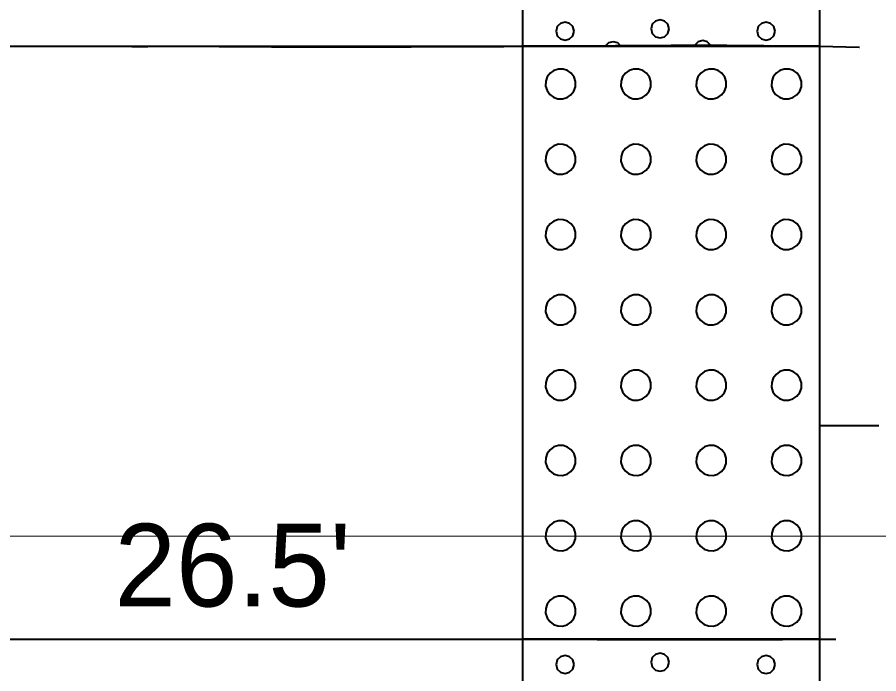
# Model space of a CAD drawing. Extents: x -582 to 653, y -817 to -3.
# Drawn here: x -72.08 to -64.82, y -720.71 to -715.18 of the extents above; entities that cross this region are included whole.
import ezdxf

# ---------------------------------------------------------------- set-up
doc = ezdxf.new("R2010")
doc.units = 0
doc.header["$LTSCALE"] = 0.4
doc.linetypes.add('LONG_DASHED', pattern=[7.5, 6, -1.5])
for name, color, linetype, lineweight in [('26', 7, 'LONG_DASHED', 40), ('27', 7, 'Continuous', 40), ('7', 7, 'Continuous', 13)]:
    doc.layers.add(name, color=color, linetype=linetype, lineweight=lineweight)

msp = doc.modelspace()

# ---------------------------------------------------------------- linework, layer by layer
at = {"layer": '26'}
for points in [[(-88.3808, -715.5103), (-71.5863, -715.4226), (-67.8189, -715.4226), (-65.3189, -715.4226), (-59.9854, -716.0123), (-56.4736, -717.0164)], [(-88.5815, -720.4304), (-71.5863, -720.4226), (-67.8189, -720.4226), (-65.3189, -720.4226), (-45.0863, -720.1526), (-41.3189, -720.1526), (-38.8189, -720.1526), (-13.429, -720.33)]]:
    msp.add_spline(points, degree=3, dxfattribs=at)
at = {"layer": '27'}
for p, q in [((-71.5863, -715.4226), (-67.8189, -715.4226)), ((-64.8189, -718.6226), (-65.3189, -718.6226)), ((-71.5863, -720.4226), (-67.8189, -720.4226))]:
    msp.add_line(p, q, dxfattribs=at)
for points in [[(-67.8189, -704.9226), (-65.3189, -704.9226), (-65.3189, -715.4226), (-67.8189, -715.4226)], [(-67.387, -715.2953), (-67.3972, -715.2572), (-67.4251, -715.2293), (-67.4632, -715.2191), (-67.5013, -715.2293), (-67.5292, -715.2572), (-67.5394, -715.2953), (-67.5292, -715.3334), (-67.5013, -715.3612), (-67.4632, -715.3715), (-67.4251, -715.3612), (-67.3972, -715.3334)], [(-66.586, -715.2757), (-66.5962, -715.2376), (-66.6241, -715.2097), (-66.6622, -715.1995), (-66.7003, -715.2097), (-66.7282, -715.2376), (-66.7384, -715.2757), (-66.7282, -715.3138), (-66.7003, -715.3417), (-66.6622, -715.3519), (-66.6241, -715.3417), (-66.5962, -715.3138)], [(-65.6924, -715.2953), (-65.7026, -715.2572), (-65.7305, -715.2293), (-65.7686, -715.2191), (-65.8067, -715.2293), (-65.8345, -715.2572), (-65.8448, -715.2953), (-65.8345, -715.3334), (-65.8067, -715.3613), (-65.7686, -715.3715), (-65.7305, -715.3613), (-65.7026, -715.3334)], [(-66.2372, -715.4134), (-66.265, -715.3855), (-66.3031, -715.3753), (-66.3412, -715.3855), (-66.3691, -715.4134), (-66.3716, -715.4226), (-66.2347, -715.4226)], [(-67.8189, -715.4226), (-65.3189, -715.4226), (-65.3189, -720.4226), (-67.8189, -720.4226)], [(-66.9922, -715.4224), (-67.0201, -715.3945), (-67.0582, -715.3843), (-67.0963, -715.3945), (-67.1242, -715.4224), (-67.1243, -715.4226), (-66.9922, -715.4226)], [(-67.3743, -715.7401), (-67.3758, -715.7204), (-67.388, -715.6827), (-67.4111, -715.6506), (-67.443, -715.6272), (-67.4805, -715.6147), (-67.5201, -715.6144), (-67.5578, -715.6262), (-67.5901, -715.6491), (-67.6138, -715.6808), (-67.6266, -715.7182), (-67.6273, -715.7577), (-67.6158, -715.7956), (-67.5932, -715.8281), (-67.5618, -715.852), (-67.5245, -715.8652), (-67.4849, -715.8662), (-67.447, -715.855), (-67.4143, -715.8327), (-67.39, -715.8015), (-67.3766, -715.7643)], [(-66.7393, -715.7401), (-66.7408, -715.7204), (-66.753, -715.6827), (-66.7761, -715.6506), (-66.808, -715.6272), (-66.8455, -715.6147), (-66.8851, -715.6144), (-66.9228, -715.6262), (-66.9551, -715.6491), (-66.9788, -715.6808), (-66.9916, -715.7182), (-66.9923, -715.7577), (-66.9808, -715.7956), (-66.9582, -715.8281), (-66.9268, -715.852), (-66.8895, -715.8652), (-66.8499, -715.8662), (-66.812, -715.855), (-66.7793, -715.8327), (-66.755, -715.8015), (-66.7416, -715.7643)], [(-66.1043, -715.7401), (-66.1058, -715.7204), (-66.118, -715.6827), (-66.1411, -715.6506), (-66.173, -715.6272), (-66.2105, -715.6147), (-66.2501, -715.6144), (-66.2878, -715.6262), (-66.3201, -715.6491), (-66.3438, -715.6808), (-66.3566, -715.7182), (-66.3573, -715.7577), (-66.3458, -715.7956), (-66.3232, -715.8281), (-66.2918, -715.852), (-66.2545, -715.8652), (-66.2149, -715.8662), (-66.177, -715.855), (-66.1443, -715.8327), (-66.12, -715.8015), (-66.1066, -715.7643)], [(-65.4693, -715.7401), (-65.4708, -715.7204), (-65.483, -715.6827), (-65.5061, -715.6506), (-65.538, -715.6272), (-65.5755, -715.6147), (-65.6151, -715.6144), (-65.6528, -715.6262), (-65.6851, -715.6491), (-65.7088, -715.6808), (-65.7216, -715.7182), (-65.7223, -715.7577), (-65.7108, -715.7956), (-65.6882, -715.8281), (-65.6568, -715.852), (-65.6195, -715.8652), (-65.5799, -715.8662), (-65.542, -715.855), (-65.5093, -715.8327), (-65.485, -715.8015), (-65.4716, -715.7643)], [(-67.3743, -716.3751), (-67.3758, -716.3554), (-67.388, -716.3177), (-67.4111, -716.2856), (-67.443, -716.2622), (-67.4805, -716.2497), (-67.5201, -716.2494), (-67.5578, -716.2612), (-67.5901, -716.2841), (-67.6138, -716.3158), (-67.6266, -716.3532), (-67.6273, -716.3927), (-67.6158, -716.4306), (-67.5932, -716.4631), (-67.5618, -716.487), (-67.5245, -716.5002), (-67.4849, -716.5012), (-67.447, -716.49), (-67.4143, -716.4677), (-67.39, -716.4365), (-67.3766, -716.3993)], [(-66.7393, -716.3751), (-66.7408, -716.3554), (-66.753, -716.3177), (-66.7761, -716.2856), (-66.808, -716.2622), (-66.8455, -716.2497), (-66.8851, -716.2494), (-66.9228, -716.2612), (-66.9551, -716.2841), (-66.9788, -716.3158), (-66.9916, -716.3532), (-66.9923, -716.3927), (-66.9808, -716.4306), (-66.9582, -716.4631), (-66.9268, -716.487), (-66.8895, -716.5002), (-66.8499, -716.5012), (-66.812, -716.49), (-66.7793, -716.4677), (-66.755, -716.4365), (-66.7416, -716.3993)], [(-66.1043, -716.3751), (-66.1058, -716.3554), (-66.118, -716.3177), (-66.1411, -716.2856), (-66.173, -716.2622), (-66.2105, -716.2497), (-66.2501, -716.2494), (-66.2878, -716.2612), (-66.3201, -716.2841), (-66.3438, -716.3158), (-66.3566, -716.3532), (-66.3573, -716.3927), (-66.3458, -716.4306), (-66.3232, -716.4631), (-66.2918, -716.487), (-66.2545, -716.5002), (-66.2149, -716.5012), (-66.177, -716.49), (-66.1443, -716.4677), (-66.12, -716.4365), (-66.1066, -716.3993)], [(-65.4693, -716.3751), (-65.4708, -716.3554), (-65.483, -716.3177), (-65.5061, -716.2856), (-65.538, -716.2622), (-65.5755, -716.2497), (-65.6151, -716.2494), (-65.6528, -716.2612), (-65.6851, -716.2841), (-65.7088, -716.3158), (-65.7216, -716.3532), (-65.7223, -716.3927), (-65.7108, -716.4306), (-65.6882, -716.4631), (-65.6568, -716.487), (-65.6195, -716.5002), (-65.5799, -716.5012), (-65.542, -716.49), (-65.5093, -716.4677), (-65.485, -716.4365), (-65.4716, -716.3993)], [(-67.3743, -717.0101), (-67.3758, -716.9904), (-67.388, -716.9527), (-67.4111, -716.9206), (-67.443, -716.8972), (-67.4805, -716.8847), (-67.5201, -716.8844), (-67.5578, -716.8962), (-67.5901, -716.9191), (-67.6138, -716.9508), (-67.6266, -716.9882), (-67.6273, -717.0277), (-67.6158, -717.0656), (-67.5932, -717.0981), (-67.5618, -717.122), (-67.5245, -717.1352), (-67.4849, -717.1362), (-67.447, -717.125), (-67.4143, -717.1027), (-67.39, -717.0715), (-67.3766, -717.0343)], [(-66.7393, -717.0101), (-66.7408, -716.9904), (-66.753, -716.9527), (-66.7761, -716.9206), (-66.808, -716.8972), (-66.8455, -716.8847), (-66.8851, -716.8844), (-66.9228, -716.8962), (-66.9551, -716.9191), (-66.9788, -716.9508), (-66.9916, -716.9882), (-66.9923, -717.0277), (-66.9808, -717.0656), (-66.9582, -717.0981), (-66.9268, -717.122), (-66.8895, -717.1352), (-66.8499, -717.1362), (-66.812, -717.125), (-66.7793, -717.1027), (-66.755, -717.0715), (-66.7416, -717.0343)], [(-66.1043, -717.0101), (-66.1058, -716.9904), (-66.118, -716.9527), (-66.1411, -716.9206), (-66.173, -716.8972), (-66.2105, -716.8847), (-66.2501, -716.8844), (-66.2878, -716.8962), (-66.3201, -716.9191), (-66.3438, -716.9508), (-66.3566, -716.9882), (-66.3573, -717.0277), (-66.3458, -717.0656), (-66.3232, -717.0981), (-66.2918, -717.122), (-66.2545, -717.1352), (-66.2149, -717.1362), (-66.177, -717.125), (-66.1443, -717.1027), (-66.12, -717.0715), (-66.1066, -717.0343)], [(-65.4693, -717.0101), (-65.4708, -716.9904), (-65.483, -716.9527), (-65.5061, -716.9206), (-65.538, -716.8972), (-65.5755, -716.8847), (-65.6151, -716.8844), (-65.6528, -716.8962), (-65.6851, -716.9191), (-65.7088, -716.9508), (-65.7216, -716.9882), (-65.7223, -717.0277), (-65.7108, -717.0656), (-65.6882, -717.0981), (-65.6568, -717.122), (-65.6195, -717.1352), (-65.5799, -717.1362), (-65.542, -717.125), (-65.5093, -717.1027), (-65.485, -717.0715), (-65.4716, -717.0343)], [(-67.3743, -717.6451), (-67.3758, -717.6254), (-67.388, -717.5877), (-67.4111, -717.5556), (-67.443, -717.5322), (-67.4805, -717.5197), (-67.5201, -717.5194), (-67.5578, -717.5312), (-67.5901, -717.5541), (-67.6138, -717.5858), (-67.6266, -717.6232), (-67.6273, -717.6627), (-67.6158, -717.7006), (-67.5932, -717.7331), (-67.5618, -717.757), (-67.5245, -717.7702), (-67.4849, -717.7712), (-67.447, -717.76), (-67.4143, -717.7377), (-67.39, -717.7065), (-67.3766, -717.6693)], [(-66.7393, -717.6451), (-66.7408, -717.6254), (-66.753, -717.5877), (-66.7761, -717.5556), (-66.808, -717.5322), (-66.8455, -717.5197), (-66.8851, -717.5194), (-66.9228, -717.5312), (-66.9551, -717.5541), (-66.9788, -717.5858), (-66.9916, -717.6232), (-66.9923, -717.6627), (-66.9808, -717.7006), (-66.9582, -717.7331), (-66.9268, -717.757), (-66.8895, -717.7702), (-66.8499, -717.7712), (-66.812, -717.76), (-66.7793, -717.7377), (-66.755, -717.7065), (-66.7416, -717.6693)], [(-66.1043, -717.6451), (-66.1058, -717.6254), (-66.118, -717.5877), (-66.1411, -717.5556), (-66.173, -717.5322), (-66.2105, -717.5197), (-66.2501, -717.5194), (-66.2878, -717.5312), (-66.3201, -717.5541), (-66.3438, -717.5858), (-66.3566, -717.6232), (-66.3573, -717.6627), (-66.3458, -717.7006), (-66.3232, -717.7331), (-66.2918, -717.757), (-66.2545, -717.7702), (-66.2149, -717.7712), (-66.177, -717.76), (-66.1443, -717.7377), (-66.12, -717.7065), (-66.1066, -717.6693)], [(-65.4693, -717.6451), (-65.4708, -717.6254), (-65.483, -717.5877), (-65.5061, -717.5556), (-65.538, -717.5322), (-65.5755, -717.5197), (-65.6151, -717.5194), (-65.6528, -717.5312), (-65.6851, -717.5541), (-65.7088, -717.5858), (-65.7216, -717.6232), (-65.7223, -717.6627), (-65.7108, -717.7006), (-65.6882, -717.7331), (-65.6568, -717.757), (-65.6195, -717.7702), (-65.5799, -717.7712), (-65.542, -717.76), (-65.5093, -717.7377), (-65.485, -717.7065), (-65.4716, -717.6693)], [(-67.3743, -718.2801), (-67.3758, -718.2604), (-67.388, -718.2227), (-67.4111, -718.1906), (-67.443, -718.1672), (-67.4805, -718.1547), (-67.5201, -718.1544), (-67.5578, -718.1662), (-67.5901, -718.1891), (-67.6138, -718.2208), (-67.6266, -718.2582), (-67.6273, -718.2977), (-67.6158, -718.3356), (-67.5932, -718.3681), (-67.5618, -718.392), (-67.5245, -718.4052), (-67.4849, -718.4062), (-67.447, -718.395), (-67.4143, -718.3727), (-67.39, -718.3415), (-67.3766, -718.3043)], [(-66.7393, -718.2801), (-66.7408, -718.2604), (-66.753, -718.2227), (-66.7761, -718.1906), (-66.808, -718.1672), (-66.8455, -718.1547), (-66.8851, -718.1544), (-66.9228, -718.1662), (-66.9551, -718.1891), (-66.9788, -718.2208), (-66.9916, -718.2582), (-66.9923, -718.2977), (-66.9808, -718.3356), (-66.9582, -718.3681), (-66.9268, -718.392), (-66.8895, -718.4052), (-66.8499, -718.4062), (-66.812, -718.395), (-66.7793, -718.3727), (-66.755, -718.3415), (-66.7416, -718.3043)], [(-66.1043, -718.2801), (-66.1058, -718.2604), (-66.118, -718.2227), (-66.1411, -718.1906), (-66.173, -718.1672), (-66.2105, -718.1547), (-66.2501, -718.1544), (-66.2878, -718.1662), (-66.3201, -718.1891), (-66.3438, -718.2208), (-66.3566, -718.2582), (-66.3573, -718.2977), (-66.3458, -718.3356), (-66.3232, -718.3681), (-66.2918, -718.392), (-66.2545, -718.4052), (-66.2149, -718.4062), (-66.177, -718.395), (-66.1443, -718.3727), (-66.12, -718.3415), (-66.1066, -718.3043)], [(-65.4693, -718.2801), (-65.4708, -718.2604), (-65.483, -718.2227), (-65.5061, -718.1906), (-65.538, -718.1672), (-65.5755, -718.1547), (-65.6151, -718.1544), (-65.6528, -718.1662), (-65.6851, -718.1891), (-65.7088, -718.2208), (-65.7216, -718.2582), (-65.7223, -718.2977), (-65.7108, -718.3356), (-65.6882, -718.3681), (-65.6568, -718.392), (-65.6195, -718.4052), (-65.5799, -718.4062), (-65.542, -718.395), (-65.5093, -718.3727), (-65.485, -718.3415), (-65.4716, -718.3043)], [(-67.3743, -718.9151), (-67.3758, -718.8954), (-67.388, -718.8577), (-67.4111, -718.8256), (-67.443, -718.8022), (-67.4805, -718.7897), (-67.5201, -718.7894), (-67.5578, -718.8012), (-67.5901, -718.8241), (-67.6138, -718.8558), (-67.6266, -718.8932), (-67.6273, -718.9327), (-67.6158, -718.9706), (-67.5932, -719.0031), (-67.5618, -719.027), (-67.5245, -719.0402), (-67.4849, -719.0412), (-67.447, -719.03), (-67.4143, -719.0077), (-67.39, -718.9765), (-67.3766, -718.9393)], [(-66.7393, -718.9151), (-66.7408, -718.8954), (-66.753, -718.8577), (-66.7761, -718.8256), (-66.808, -718.8022), (-66.8455, -718.7897), (-66.8851, -718.7894), (-66.9228, -718.8012), (-66.9551, -718.8241), (-66.9788, -718.8558), (-66.9916, -718.8932), (-66.9923, -718.9327), (-66.9808, -718.9706), (-66.9582, -719.0031), (-66.9268, -719.027), (-66.8895, -719.0402), (-66.8499, -719.0412), (-66.812, -719.03), (-66.7793, -719.0077), (-66.755, -718.9765), (-66.7416, -718.9393)], [(-66.1043, -718.9151), (-66.1058, -718.8954), (-66.118, -718.8577), (-66.1411, -718.8256), (-66.173, -718.8022), (-66.2105, -718.7897), (-66.2501, -718.7894), (-66.2878, -718.8012), (-66.3201, -718.8241), (-66.3438, -718.8558), (-66.3566, -718.8932), (-66.3573, -718.9327), (-66.3458, -718.9706), (-66.3232, -719.0031), (-66.2918, -719.027), (-66.2545, -719.0402), (-66.2149, -719.0412), (-66.177, -719.03), (-66.1443, -719.0077), (-66.12, -718.9765), (-66.1066, -718.9393)], [(-65.4693, -718.9151), (-65.4708, -718.8954), (-65.483, -718.8577), (-65.5061, -718.8256), (-65.538, -718.8022), (-65.5755, -718.7897), (-65.6151, -718.7894), (-65.6528, -718.8012), (-65.6851, -718.8241), (-65.7088, -718.8558), (-65.7216, -718.8932), (-65.7223, -718.9327), (-65.7108, -718.9706), (-65.6882, -719.0031), (-65.6568, -719.027), (-65.6195, -719.0402), (-65.5799, -719.0412), (-65.542, -719.03), (-65.5093, -719.0077), (-65.485, -718.9765), (-65.4716, -718.9393)], [(-67.3743, -719.5501), (-67.3758, -719.5304), (-67.388, -719.4927), (-67.4111, -719.4606), (-67.443, -719.4372), (-67.4805, -719.4247), (-67.5201, -719.4244), (-67.5578, -719.4362), (-67.5901, -719.4591), (-67.6138, -719.4908), (-67.6266, -719.5282), (-67.6273, -719.5677), (-67.6158, -719.6056), (-67.5932, -719.6381), (-67.5618, -719.662), (-67.5245, -719.6752), (-67.4849, -719.6762), (-67.447, -719.665), (-67.4143, -719.6427), (-67.39, -719.6115), (-67.3766, -719.5743)], [(-66.7393, -719.5501), (-66.7408, -719.5304), (-66.753, -719.4927), (-66.7761, -719.4606), (-66.808, -719.4372), (-66.8455, -719.4247), (-66.8851, -719.4244), (-66.9228, -719.4362), (-66.9551, -719.4591), (-66.9788, -719.4908), (-66.9916, -719.5282), (-66.9923, -719.5677), (-66.9808, -719.6056), (-66.9582, -719.6381), (-66.9268, -719.662), (-66.8895, -719.6752), (-66.8499, -719.6762), (-66.812, -719.665), (-66.7793, -719.6427), (-66.755, -719.6115), (-66.7416, -719.5743)], [(-66.1043, -719.5501), (-66.1058, -719.5304), (-66.118, -719.4927), (-66.1411, -719.4606), (-66.173, -719.4372), (-66.2105, -719.4247), (-66.2501, -719.4244), (-66.2878, -719.4362), (-66.3201, -719.4591), (-66.3438, -719.4908), (-66.3566, -719.5282), (-66.3573, -719.5677), (-66.3458, -719.6056), (-66.3232, -719.6381), (-66.2918, -719.662), (-66.2545, -719.6752), (-66.2149, -719.6762), (-66.177, -719.665), (-66.1443, -719.6427), (-66.12, -719.6115), (-66.1066, -719.5743)], [(-65.4693, -719.5501), (-65.4708, -719.5304), (-65.483, -719.4927), (-65.5061, -719.4606), (-65.538, -719.4372), (-65.5755, -719.4247), (-65.6151, -719.4244), (-65.6528, -719.4362), (-65.6851, -719.4591), (-65.7088, -719.4908), (-65.7216, -719.5282), (-65.7223, -719.5677), (-65.7108, -719.6056), (-65.6882, -719.6381), (-65.6568, -719.662), (-65.6195, -719.6752), (-65.5799, -719.6762), (-65.542, -719.665), (-65.5093, -719.6427), (-65.485, -719.6115), (-65.4716, -719.5743)], [(-67.3743, -720.1851), (-67.3758, -720.1654), (-67.388, -720.1277), (-67.4111, -720.0956), (-67.443, -720.0722), (-67.4805, -720.0597), (-67.5201, -720.0594), (-67.5578, -720.0712), (-67.5901, -720.0941), (-67.6138, -720.1258), (-67.6266, -720.1632), (-67.6273, -720.2027), (-67.6158, -720.2406), (-67.5932, -720.2731), (-67.5618, -720.297), (-67.5245, -720.3102), (-67.4849, -720.3112), (-67.447, -720.3), (-67.4143, -720.2777), (-67.39, -720.2465), (-67.3766, -720.2093)], [(-66.7393, -720.1851), (-66.7408, -720.1654), (-66.753, -720.1277), (-66.7761, -720.0956), (-66.808, -720.0722), (-66.8455, -720.0597), (-66.8851, -720.0594), (-66.9228, -720.0712), (-66.9551, -720.0941), (-66.9788, -720.1258), (-66.9916, -720.1632), (-66.9923, -720.2027), (-66.9808, -720.2406), (-66.9582, -720.2731), (-66.9268, -720.297), (-66.8895, -720.3102), (-66.8499, -720.3112), (-66.812, -720.3), (-66.7793, -720.2777), (-66.755, -720.2465), (-66.7416, -720.2093)], [(-66.1043, -720.1851), (-66.1058, -720.1654), (-66.118, -720.1277), (-66.1411, -720.0956), (-66.173, -720.0722), (-66.2105, -720.0597), (-66.2501, -720.0594), (-66.2878, -720.0712), (-66.3201, -720.0941), (-66.3438, -720.1258), (-66.3566, -720.1632), (-66.3573, -720.2027), (-66.3458, -720.2406), (-66.3232, -720.2731), (-66.2918, -720.297), (-66.2545, -720.3102), (-66.2149, -720.3112), (-66.177, -720.3), (-66.1443, -720.2777), (-66.12, -720.2465), (-66.1066, -720.2093)], [(-65.4693, -720.1851), (-65.4708, -720.1654), (-65.483, -720.1277), (-65.5061, -720.0956), (-65.538, -720.0722), (-65.5755, -720.0597), (-65.6151, -720.0594), (-65.6528, -720.0712), (-65.6851, -720.0941), (-65.7088, -720.1258), (-65.7216, -720.1632), (-65.7223, -720.2027), (-65.7108, -720.2406), (-65.6882, -720.2731), (-65.6568, -720.297), (-65.6195, -720.3102), (-65.5799, -720.3112), (-65.542, -720.3), (-65.5093, -720.2777), (-65.485, -720.2465), (-65.4716, -720.2093)], [(-67.8189, -720.4226), (-65.3189, -720.4226), (-65.3189, -730.4226), (-67.8189, -730.4226)], [(-67.387, -720.6353), (-67.3972, -720.5972), (-67.4251, -720.5693), (-67.4632, -720.5591), (-67.5013, -720.5693), (-67.5292, -720.5972), (-67.5394, -720.6353), (-67.5292, -720.6734), (-67.5013, -720.7012), (-67.4632, -720.7115), (-67.4251, -720.7012), (-67.3972, -720.6734)], [(-66.586, -720.6157), (-66.5962, -720.5776), (-66.6241, -720.5497), (-66.6622, -720.5395), (-66.7003, -720.5497), (-66.7282, -720.5776), (-66.7384, -720.6157), (-66.7282, -720.6538), (-66.7003, -720.6817), (-66.6622, -720.6919), (-66.6241, -720.6817), (-66.5962, -720.6538)], [(-65.6924, -720.6353), (-65.7026, -720.5972), (-65.7305, -720.5693), (-65.7686, -720.5591), (-65.8067, -720.5693), (-65.8345, -720.5972), (-65.8448, -720.6353), (-65.8345, -720.6734), (-65.8067, -720.7013), (-65.7686, -720.7115), (-65.7305, -720.7013), (-65.7026, -720.6734)]]:
    msp.add_lwpolyline(points, close=True, dxfattribs=at)
at = {"layer": '7'}
for p, q in [((-120.2623, -719.5526), (-67.8189, -719.5526)), ((-81.3332, -719.5526), (-41.3189, -719.5526)), ((-65.3189, -719.5526), (-63.5793, -719.5526))]:
    msp.add_line(p, q, dxfattribs=at)

# ---------------------------------------------------------------- texts
at = {"layer": '27'}
msp.add_text("26.5'", height=0.6976, dxfattribs=at).set_placement((-71.2623, -720.1461))

doc.saveas('drawing.dxf')
